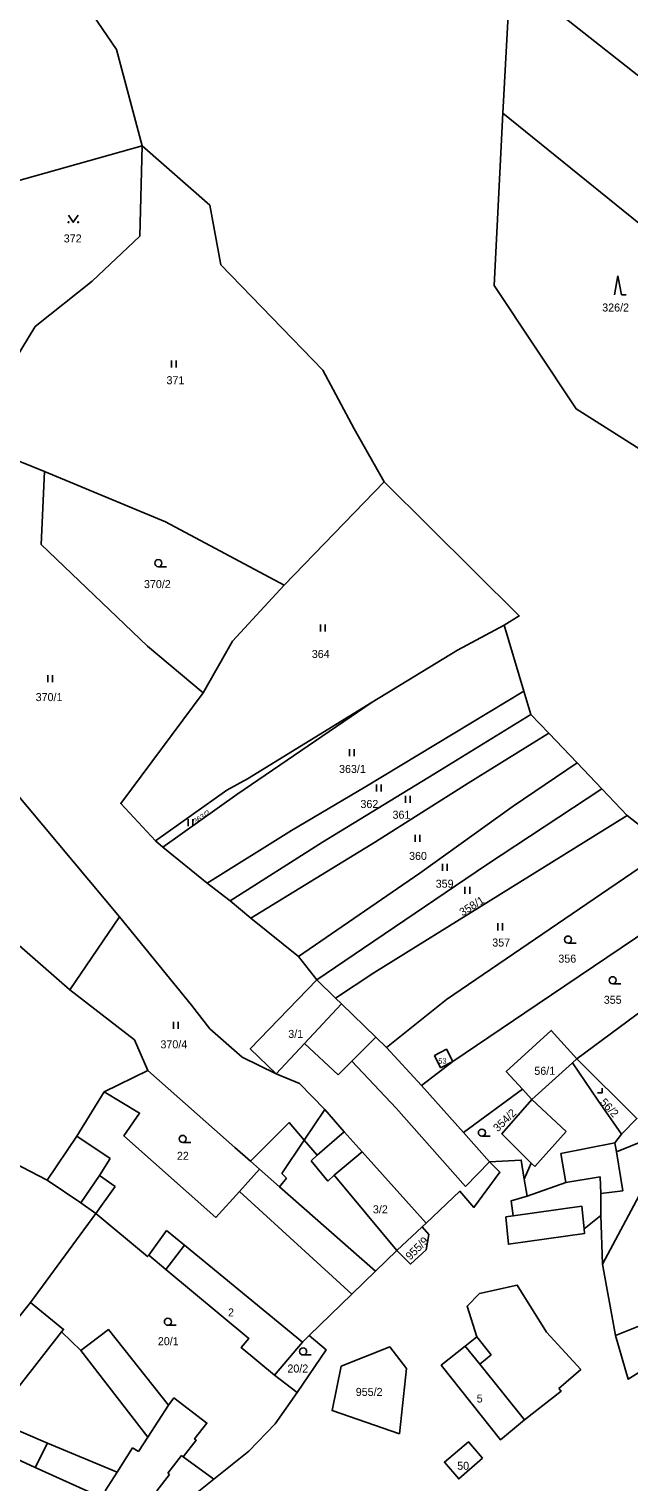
# Model space of a CAD drawing. Extents: x -7483133 to -743907, y -11317770 to -1129777.
# Drawn here: x -747956.4 to -747829, y -1130950.7 to -1130642.1 of the extents above; entities that cross this region are included whole.
import ezdxf

# ---------------------------------------------------------------- set-up
doc = ezdxf.new("R2010")
doc.units = 0
for name, color, linetype in [('Hranice parcel', 7, 'Continuous'), ('Parcelní čísla', 7, 'Continuous'), ('Vnitřní kresba', 7, 'Continuous'), ('Značky kultur', 7, 'Continuous')]:
    doc.layers.add(name, color=color, linetype=linetype)

msp = doc.modelspace()

# ---------------------------------------------------------------- linework, layer by layer
at = {"layer": 'Hranice parcel'}
for p, q in [((-747855.76, -1130660), (-747854.2, -1130630.54)), ((-747855.76, -1130660), (-747798.81, -1130706.12)), ((-747932.35, -1130666.92), (-747959.56, -1130674.56)), ((-747953.15, -1130736.09), (-747968.32, -1130729.96)), ((-747880.96, -1130738.26), (-747902.23, -1130760.25)), ((-747855.52, -1130768.71), (-747851.3, -1130782.72)), ((-747985.28, -1130773.23), (-747937.23, -1130830.7)), ((-747851.3, -1130782.72), (-747849.81, -1130787.66)), ((-747849.81, -1130787.66), (-747846.02, -1130791.65)), ((-747846.02, -1130791.65), (-747840.01, -1130797.96)), ((-747840.01, -1130797.96), (-747834.77, -1130803.46)), ((-747834.77, -1130803.46), (-747829.36, -1130809.14)), ((-747829.36, -1130809.14), (-747820.55, -1130816.09)), ((-747927.97, -1130815.84), (-747929.55, -1130814.55)), ((-747927.97, -1130815.84), (-747918.56, -1130823.54)), ((-747913.69, -1130827.28), (-747918.56, -1130823.54)), ((-747909.27, -1130830.92), (-747913.69, -1130827.28)), ((-747937.23, -1130830.7), (-747947.78, -1130846.14)), ((-747899.19, -1130839.1), (-747909.27, -1130830.92)), ((-747804.38, -1130834.32), (-747840.03, -1130860.79)), ((-747895.31, -1130844.05), (-747899.19, -1130839.1)), ((-747891.29, -1130847.94), (-747895.31, -1130844.05)), ((-747873.03, -1130866.5), (-747880.46, -1130858.39)), ((-747931.2, -1130863.28), (-747940.47, -1130867.84)), ((-747864.12, -1130876.49), (-747873.03, -1130866.5)), ((-747851.6, -1130867.26), (-747864.12, -1130876.49)), ((-747851.6, -1130867.26), (-747849.58, -1130869.48)), ((-747858.58, -1130882.72), (-747864.12, -1130876.49)), ((-747909.4, -1130882.58), (-747907.48, -1130884.27)), ((-747825.73, -1130887.83), (-747834.6, -1130904.4)), ((-747942.19, -1130893.69), (-747956.08, -1130912.6)), ((-747872.89, -1130896.5), (-747872.04, -1130895.7)), ((-747834.6, -1130904.4), (-747834.99, -1130894.09)), ((-747878.28, -1130901.53), (-747872.89, -1130896.5)), ((-747882.81, -1130905.92), (-747878.28, -1130901.53)), ((-747834.6, -1130904.4), (-747831.83, -1130919.6)), ((-747956.08, -1130912.6), (-747974.9, -1130935.77)), ((-747831.83, -1130919.6), (-747826.88, -1130917.6)), ((-747899.44, -1130931.65), (-747904.3, -1130927.98)), ((-747917.18, -1130950.1), (-747923.65, -1130945.33)), ((-747924.97, -1130956.33), (-747917.18, -1130950.1))]:
    msp.add_line(p, q, dxfattribs=at)
for points in [[(-747948.65, -1130630.54), (-747937.8, -1130646.48), (-747932.35, -1130666.92)], [(-747854.2, -1130630.54), (-747821.59, -1130656.28), (-747772.81, -1130695.9)], [(-747823.18, -1130733.56), (-747840.23, -1130722.79), (-747857.62, -1130696.55), (-747855.76, -1130660)], [(-747965.59, -1130718.16), (-747963.47, -1130718.96), (-747955.1, -1130705.31), (-747942.97, -1130695.63), (-747932.86, -1130686.09), (-747932.35, -1130666.92)], [(-747932.35, -1130666.92), (-747918.04, -1130679.51), (-747915.7, -1130692.18), (-747894.02, -1130714.58), (-747887.33, -1130727.05), (-747880.96, -1130738.26)], [(-747919.46, -1130783.07), (-747931.23, -1130773.21), (-747953.83, -1130751.57), (-747953.15, -1130736.09)], [(-747902.23, -1130760.25), (-747927.4, -1130746.77), (-747953.15, -1130736.09)], [(-747880.96, -1130738.26), (-747852.28, -1130766.74), (-747855.52, -1130768.71)], [(-747919.46, -1130783.07), (-747913.2, -1130772.11), (-747902.23, -1130760.25)], [(-747855.52, -1130768.71), (-747865.41, -1130774.06), (-747883.52, -1130785.07)], [(-747929.55, -1130814.55), (-747936.92, -1130806.6), (-747919.46, -1130783.07)], [(-747918.56, -1130823.54), (-747900.68, -1130812.35), (-747885.1, -1130803.15), (-747851.3, -1130782.72)], [(-747883.52, -1130785.07), (-747910.03, -1130801.35), (-747914.38, -1130803.79), (-747929.55, -1130814.55)], [(-747883.52, -1130785.07), (-747912.25, -1130804.68), (-747927.97, -1130815.84)], [(-747849.81, -1130787.66), (-747869.15, -1130799.59), (-747894.06, -1130814.79), (-747913.69, -1130827.28)], [(-747846.02, -1130791.65), (-747863.17, -1130802.29), (-747882.81, -1130814.71), (-747909.27, -1130830.92)], [(-747840.01, -1130797.96), (-747853.58, -1130807.15), (-747873.39, -1130821.38), (-747899.19, -1130839.1)], [(-747834.77, -1130803.46), (-747859.22, -1130819.6), (-747885.37, -1130837.32), (-747895.31, -1130844.05)], [(-747947.78, -1130846.14), (-747959.65, -1130835.75), (-748001.98, -1130807.92)], [(-747829.36, -1130809.14), (-747883.17, -1130842.59), (-747891.29, -1130847.94)], [(-747820.55, -1130816.09), (-747867.74, -1130848.23), (-747880.46, -1130858.39)], [(-747812.81, -1130825.22), (-747848.46, -1130849.27), (-747866.39, -1130861.37), (-747873.03, -1130866.5)], [(-747937.23, -1130830.7), (-747921.89, -1130849.4), (-747917.99, -1130854.46), (-747911.17, -1130860.49), (-747903.93, -1130864)], [(-747952.53, -1130886.62), (-747963.27, -1130881.1), (-747989.61, -1130862.33), (-748011.06, -1130841.51), (-748016.47, -1130840.3)], [(-747931.2, -1130863.28), (-747934.04, -1130856.8), (-747947.78, -1130846.14)], [(-747895.31, -1130844.05), (-747909.44, -1130858.68), (-747903.93, -1130864)], [(-747831.64, -1130880.59), (-747825.65, -1130878.15), (-747808.21, -1130857.46), (-747795.63, -1130843.76)], [(-747880.46, -1130858.39), (-747882.73, -1130856.2), (-747890.05, -1130849.13), (-747891.29, -1130847.94)], [(-747840.03, -1130860.79), (-747845.48, -1130854.8), (-747855.03, -1130863.49), (-747851.6, -1130867.26)], [(-747868.98, -1130862.72), (-747866.39, -1130861.37), (-747867.74, -1130858.78), (-747870.26, -1130860.14), (-747868.98, -1130862.72)], [(-747830.59, -1130876.82), (-747835.61, -1130869.57), (-747840.96, -1130861.66), (-747840.03, -1130860.79)], [(-747830.59, -1130876.82), (-747827.3, -1130873.5), (-747840.03, -1130860.79)], [(-747909.4, -1130882.58), (-747912.7, -1130879.65), (-747931.2, -1130863.28)], [(-747903.93, -1130864), (-747898.96, -1130866.03), (-747893.59, -1130871.58)], [(-747940.47, -1130867.84), (-747946.29, -1130877.28), (-747952.53, -1130886.62)], [(-747907.48, -1130884.27), (-747911.73, -1130888.98), (-747916.7, -1130894.49), (-747936.25, -1130877.17), (-747932.92, -1130872.33), (-747940.47, -1130867.84)], [(-747849.58, -1130869.48), (-747856.02, -1130876.74), (-747849.73, -1130882.95), (-747851.22, -1130886.4)], [(-747893.59, -1130871.58), (-747897.97, -1130878.1), (-747901.18, -1130874.36), (-747909.4, -1130882.58)], [(-747893.59, -1130871.58), (-747889.47, -1130876.3), (-747885.64, -1130880.57), (-747872.04, -1130895.7)], [(-747831.64, -1130880.59), (-747832, -1130878.65), (-747830.59, -1130876.82)], [(-747872.04, -1130895.7), (-747864.89, -1130888.95), (-747861.93, -1130892.38), (-747856.4, -1130884.91), (-747858.58, -1130882.72)], [(-747858.58, -1130882.72), (-747851.86, -1130882.31), (-747851.22, -1130886.4)], [(-747834.99, -1130894.09), (-747834.94, -1130889.44), (-747830.29, -1130888.84), (-747831.64, -1130880.59)], [(-747952.53, -1130886.62), (-747945.42, -1130891.38), (-747942.19, -1130893.69)], [(-747882.81, -1130905.92), (-747903.24, -1130887.99), (-747907.48, -1130884.27)], [(-747851.22, -1130886.4), (-747850.63, -1130889.96), (-747854.03, -1130890.99), (-747853.59, -1130894.17), (-747855.12, -1130894.39), (-747854.58, -1130900.2), (-747838.4, -1130897.9), (-747838.48, -1130896.91), (-747834.99, -1130894.09)], [(-747942.19, -1130893.69), (-747931.25, -1130902.83), (-747930.99, -1130902.52), (-747927.35, -1130905.55), (-747909.73, -1130920.21), (-747911.33, -1130922.13), (-747904.3, -1130927.98)], [(-747872.89, -1130896.5), (-747871.47, -1130898.11), (-747872.07, -1130901.37), (-747875.4, -1130904.41), (-747878.28, -1130901.53)], [(-747896.9, -1130919.58), (-747887.85, -1130910.81), (-747882.81, -1130905.92)], [(-747843.9, -1130930.84), (-747839.22, -1130926.8), (-747846.52, -1130918.84), (-747852.72, -1130908.9), (-747860.71, -1130910.68), (-747863.35, -1130913.36), (-747861.32, -1130919.89), (-747863.78, -1130921.85), (-747868.87, -1130925.9), (-747856.24, -1130941.74), (-747851.16, -1130937.49), (-747843.41, -1130931.39), (-747843.9, -1130930.84)], [(-747925.67, -1130932.84), (-747926.76, -1130934.36), (-747939.55, -1130918.32), (-747945.43, -1130922.74), (-747949.51, -1130918.78), (-747949.09, -1130918.27), (-747956.08, -1130912.6)], [(-747904.3, -1130927.98), (-747898.32, -1130921.01), (-747896.9, -1130919.58)], [(-747899.44, -1130931.65), (-747893.27, -1130922.65), (-747896.9, -1130919.58)], [(-747831.83, -1130919.6), (-747829.18, -1130928.84), (-747822.73, -1130924.82)], [(-747877.73, -1130940.47), (-747892.05, -1130935.51), (-747890.11, -1130926.12), (-747879.78, -1130921.99), (-747876.24, -1130926.56), (-747877.73, -1130940.47)], [(-747923.65, -1130945.33), (-747920.91, -1130941.82), (-747921.26, -1130941.54), (-747918.64, -1130938.18), (-747925.67, -1130932.84)], [(-747917.18, -1130950.1), (-747909.76, -1130944.17), (-747904.14, -1130938.37), (-747899.44, -1130931.65)], [(-747974.9, -1130935.77), (-747975.53, -1130936.55), (-747967.6, -1130941.88), (-747955.12, -1130947.63), (-747941.28, -1130953.85), (-747935.01, -1130956.79), (-747924.97, -1130956.33)], [(-747860.11, -1130945.6), (-747863.09, -1130942.14), (-747868.17, -1130946.48), (-747865.14, -1130950.05), (-747860.11, -1130945.6)]]:
    msp.add_lwpolyline(points, dxfattribs=at)
at = {"layer": 'Vnitřní kresba'}
for p, q in [((-747890.05, -1130849.13), (-747897.92, -1130857.56)), ((-747897.92, -1130857.56), (-747903.93, -1130864)), ((-747897.92, -1130857.56), (-747890.77, -1130864.23)), ((-747887.82, -1130861.32), (-747882.73, -1130856.2)), ((-747887.82, -1130861.32), (-747890.77, -1130864.23)), ((-747878.46, -1130871.28), (-747887.82, -1130861.32)), ((-747840.96, -1130861.66), (-747849.58, -1130869.48)), ((-747842.34, -1130876.27), (-747849.58, -1130869.48)), ((-747863.67, -1130887.95), (-747878.46, -1130871.28)), ((-747946.29, -1130877.28), (-747939.2, -1130881.99)), ((-747895.21, -1130881.31), (-747889.47, -1130876.3)), ((-747848.96, -1130883.68), (-747842.34, -1130876.27)), ((-747897.97, -1130878.1), (-747902.71, -1130885.17)), ((-747897.97, -1130878.1), (-747895.21, -1130881.31)), ((-747832, -1130878.65), (-747843.45, -1130880.95)), ((-747939.2, -1130881.99), (-747941.45, -1130885.62)), ((-747896.52, -1130882.45), (-747895.21, -1130881.31)), ((-747892.98, -1130886.77), (-747896.52, -1130882.45)), ((-747891.57, -1130885.56), (-747885.64, -1130880.57)), ((-747858.58, -1130882.72), (-747863.67, -1130887.95)), ((-747849.73, -1130882.95), (-747848.96, -1130883.68)), ((-747843.45, -1130880.95), (-747842.38, -1130887.09)), ((-747945.42, -1130891.38), (-747941.45, -1130885.62)), ((-747941.45, -1130885.62), (-747938.14, -1130887.93)), ((-747901.69, -1130886.19), (-747903.24, -1130887.99)), ((-747902.71, -1130885.17), (-747901.69, -1130886.19)), ((-747891.57, -1130885.56), (-747892.98, -1130886.77)), ((-747878.28, -1130901.53), (-747891.57, -1130885.56)), ((-747842.38, -1130887.09), (-747835.08, -1130885.88)), ((-747835.08, -1130885.88), (-747834.94, -1130889.44)), ((-747938.14, -1130887.93), (-747942.19, -1130893.69)), ((-747887.85, -1130910.81), (-747911.73, -1130888.98)), ((-747850.63, -1130889.96), (-747842.38, -1130887.09)), ((-747839.02, -1130892.13), (-747853.59, -1130894.17)), ((-747838.48, -1130896.91), (-747839.02, -1130892.13)), ((-747927.18, -1130897.3), (-747930.99, -1130902.52)), ((-747923.37, -1130900.43), (-747927.18, -1130897.3)), ((-747923.37, -1130900.43), (-747927.35, -1130905.55)), ((-747923.37, -1130900.43), (-747898.32, -1130921.01)), ((-747949.51, -1130918.78), (-747964.11, -1130937.48)), ((-747861.32, -1130919.89), (-747858.22, -1130923.72)), ((-747931.2, -1130941.16), (-747945.43, -1130922.74)), ((-747860.68, -1130925.7), (-747863.78, -1130921.85)), ((-747858.22, -1130923.72), (-747860.68, -1130925.7)), ((-747860.68, -1130925.7), (-747851.16, -1130937.49)), ((-747926.76, -1130934.36), (-747931.2, -1130941.16)), ((-747964.11, -1130937.48), (-747952.52, -1130942.42)), ((-747933.19, -1130944.19), (-747931.2, -1130941.16)), ((-747955.12, -1130947.63), (-747952.52, -1130942.42)), ((-747952.52, -1130942.42), (-747937.72, -1130948.61)), ((-747937.72, -1130948.61), (-747934.42, -1130943.46)), ((-747934.42, -1130943.46), (-747933.19, -1130944.19)), ((-747924, -1130945.06), (-747926.95, -1130948.85)), ((-747923.65, -1130945.33), (-747924, -1130945.06)), ((-747937.72, -1130948.61), (-747940.26, -1130952.54)), ((-747926.6, -1130949.12), (-747929.28, -1130952.56)), ((-747926.95, -1130948.85), (-747926.6, -1130949.12))]:
    msp.add_line(p, q, dxfattribs=at)
at = {"layer": 'Značky kultur'}
for p, q in [((-747831.32, -1130694.56), (-747832.07, -1130698.56)), ((-747830.57, -1130698.56), (-747831.32, -1130694.56)), ((-747830.57, -1130698.56), (-747829.57, -1130698.56)), ((-747926.16, -1130714), (-747926.16, -1130712.5)), ((-747925.16, -1130714), (-747925.16, -1130712.5)), ((-747928.95, -1130756.3), (-747927.2, -1130756.3)), ((-747894.53, -1130770.07), (-747894.53, -1130768.57)), ((-747893.53, -1130770.07), (-747893.53, -1130768.57)), ((-747952.41, -1130780.84), (-747952.41, -1130779.34)), ((-747951.41, -1130780.84), (-747951.41, -1130779.34)), ((-747888.33, -1130796.55), (-747888.33, -1130795.05)), ((-747887.33, -1130796.55), (-747887.33, -1130795.05)), ((-747882.59, -1130804.06), (-747882.59, -1130802.56)), ((-747881.59, -1130804.06), (-747881.59, -1130802.56)), ((-747876.43, -1130806.45), (-747876.43, -1130804.95)), ((-747875.43, -1130806.45), (-747875.43, -1130804.95)), ((-747922.64, -1130811.41), (-747922.64, -1130809.91)), ((-747921.64, -1130811.41), (-747921.64, -1130809.91)), ((-747874.4, -1130814.73), (-747874.4, -1130813.23)), ((-747873.4, -1130814.73), (-747873.4, -1130813.23)), ((-747868.61, -1130820.93), (-747868.61, -1130819.43)), ((-747867.61, -1130820.93), (-747867.61, -1130819.43)), ((-747863.81, -1130825.77), (-747863.81, -1130824.27)), ((-747862.81, -1130825.77), (-747862.81, -1130824.27)), ((-747856.86, -1130833.54), (-747856.86, -1130832.04)), ((-747855.86, -1130833.54), (-747855.86, -1130832.04)), ((-747841.92, -1130836.24), (-747840.17, -1130836.24)), ((-747832.44, -1130844.88), (-747830.69, -1130844.88)), ((-747925.71, -1130854.44), (-747925.71, -1130852.94)), ((-747924.71, -1130854.44), (-747924.71, -1130852.94)), ((-747835.66, -1130868.06), (-747834.66, -1130868.06)), ((-747834.66, -1130868.06), (-747834.66, -1130867.06)), ((-747860.22, -1130877.25), (-747858.47, -1130877.25)), ((-747923.77, -1130878.57), (-747922.02, -1130878.57)), ((-747926.92, -1130917.42), (-747925.17, -1130917.42)), ((-747898.2, -1130923.72), (-747896.45, -1130923.72))]:
    msp.add_line(p, q, dxfattribs=at)
msp.add_lwpolyline([(-747948.01, -1130681.65), (-747947.01, -1130683.15), (-747946.01, -1130681.65)], dxfattribs=at)
for centre, radius in [((-747948.01, -1130683.15), 0.1), ((-747946.01, -1130683.15), 0.1), ((-747928.95, -1130755.55), 0.75), ((-747841.92, -1130835.49), 0.75), ((-747832.44, -1130844.13), 0.75), ((-747923.77, -1130877.82), 0.75), ((-747860.22, -1130876.5), 0.75), ((-747926.92, -1130916.67), 0.75), ((-747898.2, -1130922.97), 0.75)]:
    msp.add_circle(centre, radius, dxfattribs=at)

# ---------------------------------------------------------------- texts
at = {"layer": 'Parcelní čísla'}
for s, height, p in [('372', 1.7, (-747949.04, -1130687.44)), ('326/2', 1.7, (-747834.66, -1130702.11)), ('371', 1.7, (-747927.21, -1130717.55)), ('370/2', 1.7, (-747932, -1130760.85)), ('364', 1.7, (-747896.35, -1130775.69)), ('370/1', 1.7, (-747955, -1130784.85)), ('363/1', 1.7, (-747890.56, -1130800.11)), ('362', 1.7, (-747886.02, -1130807.55)), ('361', 1.7, (-747879.2, -1130809.83)), ('360', 1.7, (-747875.69, -1130818.58)), ('359', 1.7, (-747870.03, -1130824.48)), ('357', 1.7, (-747858.02, -1130836.97)), ('356', 1.7, (-747843.98, -1130840.39)), ('355', 1.7, (-747834.33, -1130849.13)), ('3/1', 1.7, (-747901.35, -1130856.38)), ('370/4', 1.7, (-747928.5, -1130858.59)), ('53', 1.14, (-747869.48, -1130861.84)), ('56/1', 1.7, (-747849.08, -1130864.22)), ('22', 1.7, (-747925, -1130882.27)), ('3/2', 1.7, (-747883.37, -1130893.64)), ('2', 1.7, (-747914.15, -1130915.53)), ('20/1', 1.7, (-747929.05, -1130921.64)), ('20/2', 1.7, (-747901.53, -1130927.44)), ('955/2', 1.7, (-747887.01, -1130932.41)), ('5', 1.7, (-747861.32, -1130933.81)), ('50', 1.7, (-747865.47, -1130948.1))]:
    msp.add_text(s, height=height, dxfattribs=at).set_placement(p)
for s, height, rotation, p in [('363/2', 1.14, 34, (-747921.06, -1130811.04)), ('358/1', 1.7, 32, (-747864.34, -1130830.6)), ('56/2', 1.7, 313, (-747835.26, -1130870.17)), ('354/2', 1.7, 44, (-747856.85, -1130876.45)), ('955/9', 1.7, 45, (-747875.44, -1130903.68))]:
    msp.add_text(s, height=height, rotation=rotation, dxfattribs=at).set_placement(p)

doc.saveas('drawing.dxf')
